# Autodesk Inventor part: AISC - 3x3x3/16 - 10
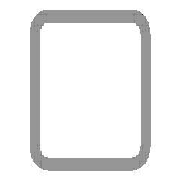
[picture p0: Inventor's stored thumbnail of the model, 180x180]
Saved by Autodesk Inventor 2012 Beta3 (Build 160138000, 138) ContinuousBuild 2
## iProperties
Created: 2011-01
Part Number: AISC - 3x3x3/16 - 10
Material: Steel, Mild
Description: Tube
Document SubType Name: Modeling
Standard: ANSI
Designer: Beta-8540w
Standards Organization: ANSI
Language: en-US
Size Designation: 3x3x3/16
Categories: <MemberInstance><Categories><Category DisplayName="Structural Shapes" InternalName="089c4875-fa83-4c05-b084-43b9cc11f5ed" Mnemonic="GRDR"><CategoryParameter Dis
Stock Number: 3x3x3/16
Density: 7.86 g/cm^3
IsCustomPart: 1
_CCFamilyMember: 9
_CCFamilyDisplayName: ANSI AISC (Square) - Tube
_FrameMemberDoc: Frame Member File
_Version: 15.0.0
_GetPNFromCC: 1
G_L: 10.000 in
G_W: 3.000 in
G_H: 3.000 in
Author: Beta-8540w
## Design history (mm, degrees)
node "Start plane"
node "End plane"
sketch "Sketch"
  geometry: L1 (-38.1, -28.575)-(-38.1, 28.575); L2 (-28.575, 38.1)-(28.575, 38.1); L3 (38.1, 28.575)-(38.1, -28.575); L4 (28.575, -38.1)-(-28.575, -38.1); L5 (-28.575, 33.337)-(28.575, 33.338); L6 (33.338, 28.575)-(33.338, -28.575); L7 (28.575, -33.337)-(-28.575, -33.338); L8 (-33.338, -28.575)-(-33.338, 28.575); L9 (0, 56.102)-(0, -56.102) reference; L10 (-56.102, 0)-(56.102, 0) reference; A1 r 9.525 centre (-28.575, -28.575) between (-38.1, -28.575) and (-28.575, -38.1); A2 r 9.525 centre (-28.575, 28.575) between (-28.575, 38.1) and (-38.1, 28.575); A3 r 9.525 centre (28.575, 28.575) between (38.1, 28.575) and (28.575, 38.1); A4 r 9.525 centre (28.575, -28.575) between (28.575, -38.1) and (38.1, -28.575); A5 r 4.763 centre (-28.575, 28.575) between (-28.575, 33.337) and (-33.338, 28.575); A6 r 4.763 centre (28.575, 28.575) between (33.338, 28.575) and (28.575, 33.338); A7 r 4.763 centre (28.575, -28.575) between (28.575, -33.337) and (33.338, -28.575); A8 r 4.763 centre (-28.575, -28.575) between (-33.338, -28.575) and (-28.575, -33.338)
  constraints: 16 end point, 16 point on circle, 8 centre point, 8 tangent, 4 parallel, 3 equal radius, 2 perpendicular, 7 other
  dimensions: "d10" = 76.2 distance between parallel lines of L2 L4 (= G_H); "d11" = 76.2 distance between parallel lines of L1 L3 (= G_W); "d12" = 4.7625 distance between parallel lines of L3 L6 (= G_T); "d15" = 38.1 distance between parallel lines of L2 L10 (= 0.5 x d10); "d16" = 38.1 distance between parallel lines of L9 L3 (= 0.5 x d11); "d17" = 9.525 radius of A1 (= G_IR)
extrude "Body" new body sketch "Sketch" stored distance "d3" = 254 (= G_L); taper "d4" = 0 deg
node "Driven Length"
  sketch "Sketch3"
    geometry: L1 (0, 0)-(10, 0) reference
    constraints: 2 end point, 1 horizontal
  workplane "Work Plane3"
  sketch "Sketch4"
    geometry: L1 (-2, 0)-(12, 0) reference; L2 (-2, 254)-(12, 254) reference
    dimensions: "d19" = 254 distance between parallel lines of L1 L2 (derived)
body "Solid1"
other parameters: "G_W" = 76.2 [user parameter; used in 1 equation term], "G_H" = 76.2 [user parameter; used in 1 equation term], "G_T" = 4.7625 [user parameter; used in 1 equation term], "G_IR" = 9.525 [user parameter; used in 1 equation term], "G_L" = 254 (= d19) [user parameter; used in 1 equation term], "G_OFFSET_START" = 0 [user parameter; used in 1 equation term], "G_OFFSET_END" = 0 [user parameter; used in 1 equation term], "d13" = 0 (computed from G_OFFSET_START), "d14" = 254 (= G_OFFSET_END + B_L), "B_L" = 254 [user parameter; used in 1 equation term], "d18" = 90 deg
